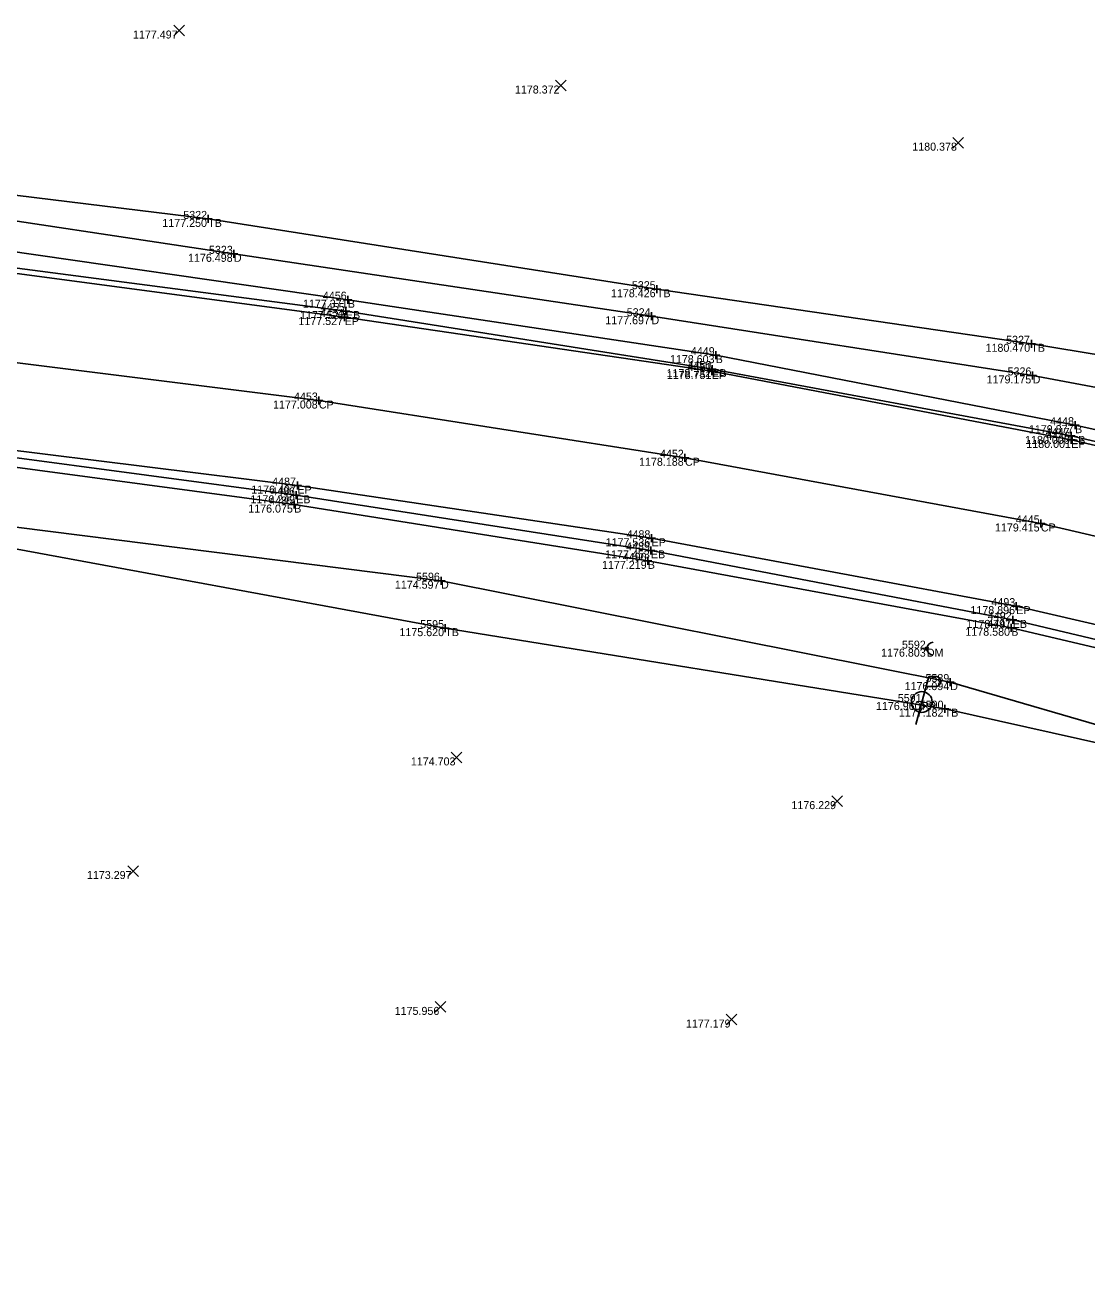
# Model space of a CAD drawing. Extents: x 2044996 to 2050343, y 455232 to 458054.
# Drawn here: x 2046787.3 to 2046920.1, y 457158.4 to 457315.9 of the extents above; entities that cross this region are included whole.
import ezdxf

# ---------------------------------------------------------------- set-up
doc = ezdxf.new("R2010")
doc.units = 0
for name, color, linetype in [('DR_X_Ditch', 7, 'Continuous'), ('DT_X_Contour_Minor', 7, 'Continuous'), ('DT_X_Contour_Text', 7, 'Continuous'), ('DT_X_Island', 7, 'Continuous'), ('DT_X_Spot_Elev', 7, 'Continuous'), ('DT_X_Triangles', 7, 'Continuous'), ('DT_X_Void', 7, 'Continuous'), ('PV_X_COP', 7, 'Continuous'), ('PV_X_EOP', 7, 'Continuous'), ('PV_X_Shoulder_Aggregate', 7, 'Continuous'), ('SV_X_Break_Lines', 7, 'Continuous'), ('SV_X_Top_of_Bank', 7, 'Continuous'), ('UT_X_Electric_Cells', 7, 'Continuous')]:
    doc.layers.add(name, color=color, linetype=linetype)

msp = doc.modelspace()

# ---------------------------------------------------------------- linework, layer by layer
at = {"layer": 'DR_X_Ditch'}
for points in [[(2046652.09, 457304.73), (2046697.72, 457300.76), (2046749.85, 457295.15), (2046773.58, 457293.27), (2046813.42, 457287.29), (2046865.63, 457279.49), (2046913.29, 457272.1), (2046945.7, 457266), (2046955.45, 457263.32), (2046957.87, 457262.51), (2047003.84, 457250.36), (2047016.8, 457245.89), (2047017.67, 457245.73), (2047064.32, 457227.1), (2047106.55, 457210.85), (2047146.99, 457194.6), (2047185.37, 457179.96), (2047230.91, 457162.64)], [(2046965.68, 457219.12), (2046952.44, 457224.82), (2046926.17, 457227.03), (2046902.99, 457233.78), (2046839.32, 457246.45), (2046782.21, 457253.65)]]:
    msp.add_lwpolyline(points, dxfattribs=at)
at = {"layer": 'DT_X_Island'}
msp.add_circle((2046900.06, 457237.96), 0.2, dxfattribs=at)
msp.add_arc((2046900.86, 457237.96), 0.8, 90, 270, dxfattribs=at)
at = {"layer": 'DT_X_Spot_Elev'}
for p, q in [((2046805.92, 457314.52), (2046807.25, 457315.85)), ((2046805.92, 457315.85), (2046807.25, 457314.52)), ((2046853.62, 457307.66), (2046854.96, 457308.99)), ((2046853.62, 457308.99), (2046854.96, 457307.66)), ((2046903.31, 457300.51), (2046904.64, 457301.84)), ((2046903.31, 457301.84), (2046904.64, 457300.51)), ((2046840.6, 457223.7), (2046841.94, 457225.03)), ((2046840.6, 457225.03), (2046841.94, 457223.7)), ((2046888.18, 457218.25), (2046889.51, 457219.58)), ((2046888.18, 457219.58), (2046889.51, 457218.25)), ((2046800.16, 457209.51), (2046801.49, 457210.84)), ((2046800.16, 457210.84), (2046801.49, 457209.51)), ((2046838.6, 457192.53), (2046839.94, 457193.87)), ((2046838.6, 457193.87), (2046839.94, 457192.53)), ((2046874.99, 457190.95), (2046876.32, 457192.29)), ((2046874.99, 457192.29), (2046876.32, 457190.95))]:
    msp.add_line(p, q, dxfattribs=at)
at = {"layer": 'DT_X_Void'}
for p, q in [((2046809.71, 457291.65), (2046810.71, 457291.65)), ((2046810.21, 457292.15), (2046810.21, 457291.15)), ((2046810.21, 457291.65), (2046810.21, 457291.65)), ((2046812.92, 457287.29), (2046813.92, 457287.29)), ((2046813.42, 457287.79), (2046813.42, 457286.79)), ((2046813.42, 457287.29), (2046813.42, 457287.29)), ((2046827.67, 457282.06), (2046827.67, 457281.06)), ((2046865.81, 457282.87), (2046866.81, 457282.87)), ((2046866.31, 457283.37), (2046866.31, 457282.37)), ((2046866.31, 457282.87), (2046866.31, 457282.87)), ((2046827.17, 457281.56), (2046828.17, 457281.56)), ((2046827.43, 457280.64), (2046827.43, 457279.64)), ((2046827.67, 457281.56), (2046827.67, 457281.56)), ((2046826.77, 457279.39), (2046827.77, 457279.39)), ((2046826.93, 457280.14), (2046827.93, 457280.14)), ((2046827.27, 457279.89), (2046827.27, 457278.89)), ((2046827.27, 457279.39), (2046827.27, 457279.39)), ((2046827.43, 457280.14), (2046827.43, 457280.14)), ((2046865.13, 457279.49), (2046866.13, 457279.49)), ((2046865.63, 457279.99), (2046865.63, 457278.99)), ((2046865.63, 457279.49), (2046865.63, 457279.49)), ((2046912.63, 457276.05), (2046913.63, 457276.05)), ((2046913.13, 457276.55), (2046913.13, 457275.55)), ((2046913.13, 457276.05), (2046913.13, 457276.05)), ((2046873.16, 457274.63), (2046874.16, 457274.63)), ((2046873.66, 457275.13), (2046873.66, 457274.13)), ((2046873.66, 457274.63), (2046873.66, 457274.63)), ((2046872.67, 457272.65), (2046873.67, 457272.65)), ((2046872.74, 457272.88), (2046873.74, 457272.88)), ((2046873.17, 457273.15), (2046873.17, 457272.15)), ((2046873.17, 457272.65), (2046873.17, 457272.65)), ((2046873.24, 457273.38), (2046873.24, 457272.38)), ((2046873.24, 457272.88), (2046873.24, 457272.88)), ((2046913.29, 457272.6), (2046913.29, 457271.6)), ((2046912.79, 457272.1), (2046913.79, 457272.1)), ((2046913.29, 457272.1), (2046913.29, 457272.1)), ((2046824.05, 457269.46), (2046824.05, 457268.46)), ((2046823.55, 457268.96), (2046824.55, 457268.96)), ((2046824.05, 457268.96), (2046824.05, 457268.96)), ((2046918.59, 457266.38), (2046918.59, 457265.38)), ((2046918.09, 457265.88), (2046919.09, 457265.88)), ((2046918.09, 457265.04), (2046918.09, 457264.04)), ((2046918.59, 457265.88), (2046918.59, 457265.88)), ((2046917.59, 457264.54), (2046918.59, 457264.54)), ((2046917.61, 457264.04), (2046918.61, 457264.04)), ((2046918.09, 457264.54), (2046918.09, 457264.54)), ((2046918.11, 457264.54), (2046918.11, 457263.54)), ((2046918.11, 457264.04), (2046918.11, 457264.04)), ((2046869.32, 457261.81), (2046870.32, 457261.81)), ((2046869.82, 457262.31), (2046869.82, 457261.31)), ((2046869.82, 457261.81), (2046869.82, 457261.81)), ((2046820.87, 457258.33), (2046821.87, 457258.33)), ((2046821.37, 457258.83), (2046821.37, 457257.83)), ((2046821.37, 457258.33), (2046821.37, 457258.33)), ((2046820.71, 457257.12), (2046821.71, 457257.12)), ((2046821.21, 457257.62), (2046821.21, 457256.62)), ((2046821.21, 457257.12), (2046821.21, 457257.12)), ((2046820.47, 457255.96), (2046821.47, 457255.96)), ((2046820.97, 457256.46), (2046820.97, 457255.46)), ((2046820.97, 457255.96), (2046820.97, 457255.96)), ((2046913.82, 457253.6), (2046914.82, 457253.6)), ((2046914.32, 457254.1), (2046914.32, 457253.1)), ((2046914.32, 457253.6), (2046914.32, 457253.6)), ((2046865.64, 457252.25), (2046865.64, 457251.25)), ((2046865.14, 457251.75), (2046866.14, 457251.75)), ((2046865.56, 457250.74), (2046865.56, 457249.74)), ((2046865.64, 457251.75), (2046865.64, 457251.75)), ((2046864.67, 457248.93), (2046865.67, 457248.93)), ((2046865.06, 457250.24), (2046866.06, 457250.24)), ((2046865.17, 457249.43), (2046865.17, 457248.43)), ((2046865.17, 457248.93), (2046865.17, 457248.93)), ((2046865.56, 457250.24), (2046865.56, 457250.24)), ((2046838.82, 457246.45), (2046839.82, 457246.45)), ((2046839.32, 457246.95), (2046839.32, 457245.95)), ((2046839.32, 457246.45), (2046839.32, 457246.45)), ((2046910.74, 457243.27), (2046911.74, 457243.27)), ((2046911.24, 457243.77), (2046911.24, 457242.77)), ((2046911.24, 457243.27), (2046911.24, 457243.27)), ((2046839.85, 457241.02), (2046839.85, 457240.02)), ((2046910.3, 457241.55), (2046911.3, 457241.55)), ((2046910.62, 457241.07), (2046910.62, 457240.07)), ((2046910.8, 457242.05), (2046910.8, 457241.05)), ((2046910.8, 457241.55), (2046910.8, 457241.55)), ((2046839.35, 457240.52), (2046840.35, 457240.52)), ((2046839.85, 457240.52), (2046839.85, 457240.52)), ((2046910.12, 457240.57), (2046911.12, 457240.57)), ((2046910.62, 457240.57), (2046910.62, 457240.57)), ((2046902.49, 457233.78), (2046903.49, 457233.78)), ((2046902.99, 457234.28), (2046902.99, 457233.28)), ((2046902.99, 457233.78), (2046902.99, 457233.78)), ((2046901.79, 457230.46), (2046902.79, 457230.46)), ((2046902.29, 457230.96), (2046902.29, 457229.96)), ((2046902.29, 457230.46), (2046902.29, 457230.46))]:
    msp.add_line(p, q, dxfattribs=at)
at = {"layer": 'PV_X_COP'}
msp.add_lwpolyline([(2047612.39, 456999.11), (2047580.09, 457011.53), (2047538.37, 457027.53), (2047496.01, 457043.83), (2047451.82, 457060.1), (2047409.77, 457076.51), (2047364.77, 457093.97), (2047313.94, 457114.01), (2047268.54, 457131.55), (2047222.12, 457149.92), (2047177.7, 457167.48), (2047132.78, 457184.84), (2047088.94, 457201.35), (2047045.02, 457217.22), (2047000.47, 457231.97), (2046961.14, 457242.7), (2046914.32, 457253.6), (2046869.82, 457261.81), (2046824.05, 457268.96), (2046778.68, 457274.62), (2046733.92, 457279.83), (2046684.61, 457284.92), (2046649.61, 457288.12)], dxfattribs=at)
at = {"layer": 'PV_X_EOP'}
for p, q in [((2046827.27, 457279.39), (2046780.32, 457285.64)), ((2046873.17, 457272.65), (2046827.27, 457279.39)), ((2046918.11, 457264.04), (2046873.17, 457272.65)), ((2046775.92, 457263.99), (2046821.37, 457258.33)), ((2046965.14, 457253.04), (2046918.11, 457264.04)), ((2046821.37, 457258.33), (2046865.64, 457251.75)), ((2046865.64, 457251.75), (2046911.24, 457243.27)), ((2046911.24, 457243.27), (2046953.83, 457233.32))]:
    msp.add_line(p, q, dxfattribs=at)
at = {"layer": 'PV_X_Shoulder_Aggregate'}
for p, q in [((2046827.43, 457280.14), (2046780.32, 457286.27)), ((2046873.24, 457272.88), (2046827.43, 457280.14)), ((2046918.09, 457264.54), (2046873.24, 457272.88)), ((2046775.91, 457263.17), (2046821.21, 457257.12)), ((2046965.27, 457253.79), (2046918.09, 457264.54)), ((2046821.21, 457257.12), (2046865.56, 457250.24)), ((2046865.56, 457250.24), (2046910.8, 457241.55)), ((2046910.8, 457241.55), (2046953.53, 457231.47))]:
    msp.add_line(p, q, dxfattribs=at)
at = {"layer": 'SV_X_Break_Lines'}
for points in [[(2047227.37, 457161.69), (2047183.55, 457178.86), (2047137.31, 457196.49), (2047094.49, 457213.08), (2047049.99, 457229.63), (2047005.1, 457243.65), (2046965.33, 457255.5), (2046918.59, 457265.88), (2046873.66, 457274.63), (2046827.67, 457281.56), (2046780.24, 457288.39), (2046735.28, 457292.81), (2046686.23, 457298.46), (2046651.06, 457301.99)], [(2046644.99, 457274.79), (2046684.79, 457271.32), (2046731.45, 457265.98), (2046776.36, 457261.92), (2046820.97, 457255.96), (2046865.17, 457248.93), (2046910.62, 457240.57), (2046953.49, 457230.48), (2046996.08, 457218.34), (2047041.05, 457204.36), (2047086.23, 457188.11), (2047130.38, 457171.33), (2047171.93, 457154.51), (2047216.75, 457137.04), (2047260.77, 457120.17), (2047304.38, 457102.94), (2047349.36, 457085.13), (2047391.24, 457069.28), (2047438.05, 457051.14), (2047480.2, 457035.91), (2047522.53, 457019.68), (2047543.14, 457011.06)]]:
    msp.add_lwpolyline(points, dxfattribs=at)
at = {"layer": 'SV_X_Top_of_Bank'}
for points in [[(2046651.93, 457311.46), (2046700.58, 457305.72), (2046746.85, 457300.37), (2046773.13, 457296.21), (2046810.21, 457291.65), (2046866.31, 457282.87), (2046913.13, 457276.05), (2046946.87, 457270.5), (2046956.84, 457268.66), (2047005.28, 457255.73), (2047019.97, 457251.51), (2047064.03, 457231.46), (2047107.63, 457215.29), (2047146.99, 457200.96), (2047188.63, 457185.75), (2047229.81, 457169.99), (2047277.5, 457150.03), (2047328.36, 457129.78), (2047359.21, 457118.11), (2047442.14, 457085.97), (2047488.03, 457067.35), (2047530.83, 457050.42), (2047563.67, 457038.95)], [(2046967.26, 457216.48), (2046951.44, 457222.54), (2046925.97, 457225.16), (2046902.29, 457230.46), (2046839.85, 457240.52), (2046781.98, 457251.18)]]:
    msp.add_lwpolyline(points, dxfattribs=at)
at = {"layer": 'UT_X_Electric_Cells'}
for p, q in [((2046900.29, 457234.49), (2046898.68, 457228.49)), ((2046899.95, 457233.22), (2046901.14, 457233.22)), ((2046900.29, 457234.49), (2046901.14, 457234.49))]:
    msp.add_line(p, q, dxfattribs=at)
msp.add_circle((2046899.43, 457231.29), 1.3, dxfattribs=at)
msp.add_arc((2046901.15, 457233.86), 0.638, 268.8767, 91.1233, dxfattribs=at)

# ---------------------------------------------------------------- texts
at = {"layer": 'DT_X_Contour_Minor'}
for s, p in [('1177.497', (2046800.81, 457314.19)), ('1178.372', (2046848.56, 457307.32)), ('1180.378', (2046898.24, 457300.18)), ('1177.250', (2046804.48, 457290.65)), ('1176.498', (2046807.69, 457286.29)), ('1178.426', (2046860.57, 457281.87)), ('1177.371', (2046822.06, 457280.56)), ('1177.527', (2046821.49, 457278.39)), ('1177.522', (2046821.7, 457279.14)), ('1177.697', (2046859.86, 457278.49)), ('1180.470', (2046907.4, 457275.05)), ('1178.603', (2046867.94, 457273.63)), ('1178.732', (2046867.51, 457271.88)), ('1178.751', (2046867.55, 457271.65)), ('1179.175', (2046907.54, 457271.1)), ('1177.008', (2046818.32, 457267.96)), ('1179.877', (2046912.82, 457264.88)), ('1180.000', (2046912.35, 457263.54)), ('1180.001', (2046912.5, 457263.04)), ('1178.188', (2046864.08, 457260.81)), ('1176.407', (2046815.59, 457257.33)), ('1176.249', (2046815.49, 457256.12)), ('1176.075', (2046815.22, 457254.96)), ('1179.415', (2046908.58, 457252.6)), ('1177.536', (2046859.9, 457250.75)), ('1177.219', (2046859.45, 457247.93)), ('1177.453', (2046859.84, 457249.24)), ('1174.597', (2046833.55, 457245.45)), ('1178.896', (2046905.51, 457242.27)), ('1178.747', (2046905.02, 457240.55)), ('1175.620', (2046834.12, 457239.52)), ('1178.580', (2046904.88, 457239.57)), ('1176.803', (2046894.34, 457236.96)), ('1176.094', (2046897.28, 457232.78)), ('1176.960', (2046893.7, 457230.29)), ('1177.182', (2046896.56, 457229.46)), ('1174.703', (2046835.55, 457223.37)), ('1176.229', (2046883.13, 457217.91)), ('1173.297', (2046795.05, 457209.18)), ('1175.956', (2046833.53, 457192.2)), ('1177.179', (2046869.94, 457190.62))]:
    msp.add_text(s, height=1, dxfattribs=at).set_placement(p)
at = {"layer": 'DT_X_Contour_Text'}
for s, p in [('TB', (2046810.21, 457290.65)), ('D', (2046813.42, 457286.29)), ('TB', (2046866.31, 457281.87)), ('B', (2046827.67, 457280.56)), ('EP', (2046827.27, 457278.39)), ('EB', (2046827.43, 457279.14)), ('D', (2046865.63, 457278.49)), ('TB', (2046913.13, 457275.05)), ('B', (2046873.66, 457273.63)), ('EP', (2046873.17, 457271.65)), ('EB', (2046873.24, 457271.88)), ('D', (2046913.29, 457271.1)), ('CP', (2046824.05, 457267.96)), ('B', (2046918.59, 457264.88)), ('EB', (2046918.09, 457263.54)), ('EP', (2046918.11, 457263.04)), ('CP', (2046869.82, 457260.81)), ('EP', (2046821.37, 457257.33)), ('EB', (2046821.21, 457256.12)), ('B', (2046820.97, 457254.96)), ('CP', (2046914.32, 457252.6)), ('EP', (2046865.64, 457250.75)), ('B', (2046865.17, 457247.93)), ('EB', (2046865.56, 457249.24)), ('D', (2046839.32, 457245.45)), ('EP', (2046911.24, 457242.27)), ('EB', (2046910.8, 457240.55)), ('TB', (2046839.85, 457239.52)), ('B', (2046910.62, 457239.57)), ('DM', (2046900.06, 457236.96)), ('D', (2046902.99, 457232.78)), ('PP', (2046899.43, 457230.29)), ('TB', (2046902.29, 457229.46))]:
    msp.add_text(s, height=1, dxfattribs=at).set_placement(p)
at = {"layer": 'DT_X_Triangles'}
for s, p in [('5322', (2046807.1, 457291.65)), ('5323', (2046810.31, 457287.29)), ('5325', (2046863.18, 457282.87)), ('4456', (2046824.55, 457281.56)), ('4454', (2046824.18, 457279.39)), ('4455', (2046824.3, 457280.14)), ('5324', (2046862.54, 457279.49)), ('4449', (2046870.56, 457274.63)), ('5327', (2046909.97, 457276.05)), ('4450', (2046870.12, 457272.88)), ('4451', (2046870.17, 457272.65)), ('5326', (2046910.16, 457272.1)), ('4453', (2046820.94, 457268.96)), ('4448', (2046915.48, 457265.88)), ('4447', (2046914.93, 457264.54)), ('4446', (2046914.99, 457264.04)), ('4452', (2046866.7, 457261.81)), ('4487', (2046818.21, 457258.33)), ('4485', (2046817.84, 457255.96)), ('4486', (2046818.08, 457257.12)), ('4445', (2046911.19, 457253.6)), ('4488', (2046862.52, 457251.75)), ('4489', (2046862.46, 457250.24)), ('4490', (2046862.05, 457248.93)), ('5596', (2046836.2, 457246.45)), ('4493', (2046908.14, 457243.27)), ('4492', (2046907.68, 457241.55)), ('5595', (2046836.72, 457240.52)), ('4491', (2046907.62, 457240.57)), ('5592', (2046896.95, 457237.96)), ('5589', (2046899.89, 457233.78)), ('5591', (2046896.43, 457231.29)), ('5590', (2046899.17, 457230.46))]:
    msp.add_text(s, height=1, dxfattribs=at).set_placement(p)

doc.saveas('drawing.dxf')
